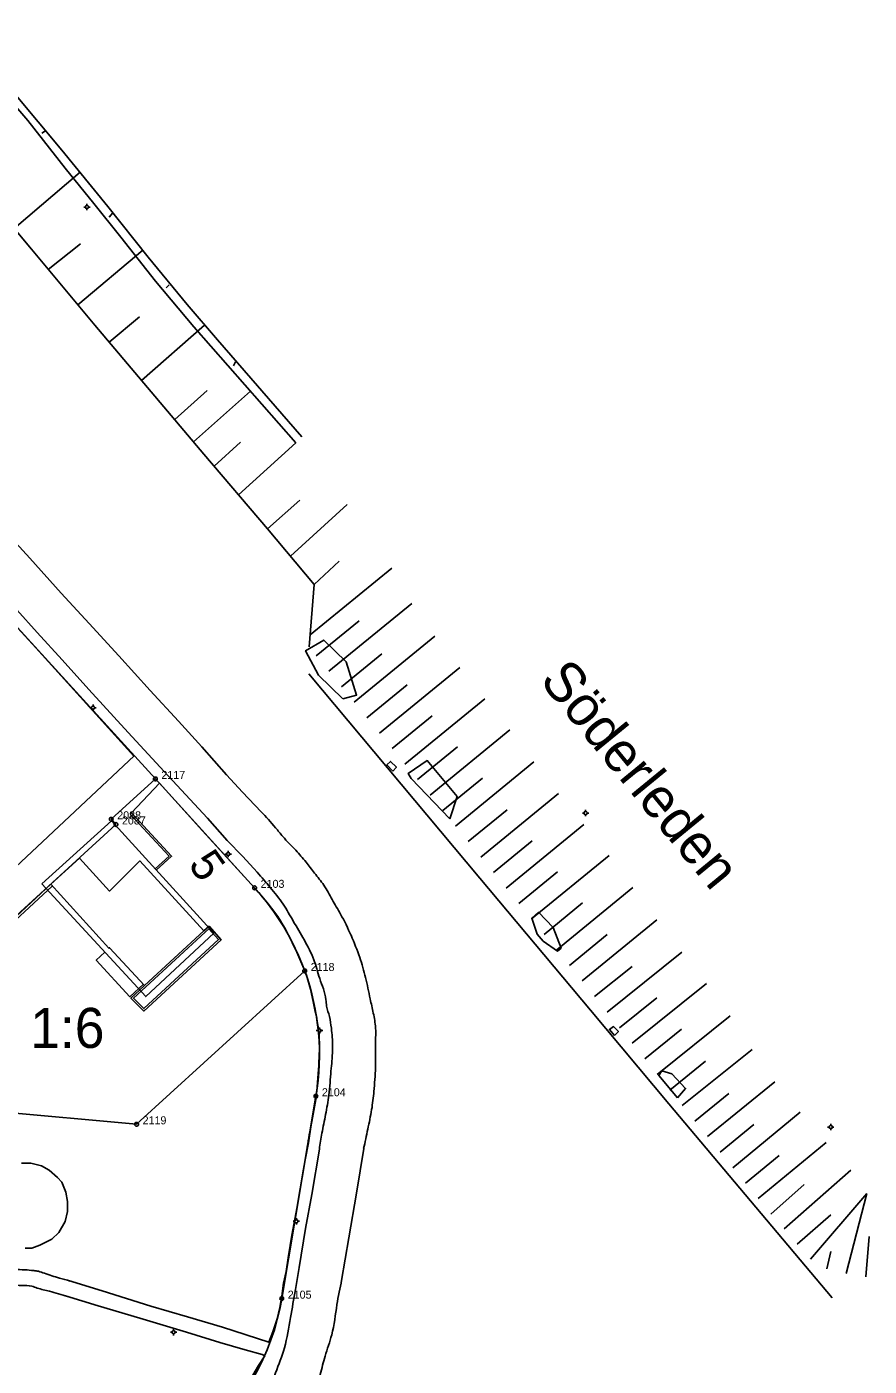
# Model space of a CAD drawing. Extents: x 1517693 to 1518189, y 6494860 to 6495280.
# Drawn here: x 1518083.9 to 1518189.2, y 6495063.4 to 6495230.8 of the extents above; entities that cross this region are included whole.
import ezdxf

# ---------------------------------------------------------------- set-up
doc = ezdxf.new("R2010")
doc.units = 0
for name, color, linetype in [('adress', 7, 'Continuous'), ('bostadshus', 7, 'Continuous'), ('fastighetsbeteckning', 7, 'Continuous'), ('gatunamn', 7, 'Continuous'), ('gc_vag', 7, 'Continuous'), ('grans', 7, 'Continuous'), ('granspunkt', 7, 'Continuous'), ('granspunkt_text', 7, 'Continuous'), ('kvartersgrans', 7, 'Continuous'), ('kvartersgrans_utan_fastgr', 7, 'Continuous'), ('planteringskant', 7, 'Continuous'), ('skarmtak', 7, 'Continuous'), ('slant_skraffering', 7, 'Continuous'), ('slantfot', 7, 'Continuous'), ('slantkron', 7, 'Continuous'), ('staket', 7, 'Continuous'), ('stenmur', 7, 'Continuous'), ('stolpe_belysning', 7, 'Continuous'), ('trappa_byggnad', 7, 'Continuous'), ('vagkant', 7, 'Continuous')]:
    doc.layers.add(name, color=color, linetype=linetype)

msp = doc.modelspace()

# ---------------------------------------------------------------- linework, layer by layer
at = {"layer": 'bostadshus'}
msp.add_lwpolyline([(1518086.89, 6495123.66), (1518090.48, 6495126.91), (1518094.25, 6495122.81), (1518098.04, 6495126.57), (1518106.03, 6495117.83), (1518098.62, 6495111.02), (1518094.24, 6495115.73), (1518094.15, 6495115.66), (1518086.88, 6495123.66)], dxfattribs=at)
at = {"layer": 'gc_vag'}
for p, q in [((1518085.02, 6495153.19), (1518097.28, 6495139.69)), ((1518100.47, 6495136.3), (1518096.97, 6495132.58))]:
    msp.add_line(p, q, dxfattribs=at)
for points in [[(1518080.55, 6495158.09), (1518082.73, 6495155.72), (1518085.02, 6495153.19)], [(1518097.3, 6495139.7), (1518079.77, 6495123.29), (1518069.67, 6495123.88)], [(1518100.47, 6495136.3), (1518105.84, 6495130.34), (1518112.4, 6495123.17)], [(1518118.38, 6495087.34), (1518118.71, 6495089.22), (1518119.1, 6495091.32), (1518119.41, 6495093.33), (1518119.63, 6495094.49)], [(1518116.59, 6495076.95), (1518117.01, 6495079.78), (1518117.66, 6495083.14), (1518118.07, 6495085.6), (1518118.38, 6495087.34)], [(1518108.34, 6495068.28), (1518114.17, 6495066.44), (1518114.67, 6495067.72), (1518115.19, 6495069.34), (1518115.54, 6495070.77), (1518115.78, 6495072.17), (1518116, 6495073.78), (1518116.31, 6495075.24), (1518116.59, 6495076.95)], [(1518089.11, 6495074.12), (1518093.31, 6495072.82), (1518099.4, 6495070.92), (1518104, 6495069.59), (1518108.36, 6495068.28)], [(1518088.71, 6495072.21), (1518092.82, 6495070.95), (1518098.04, 6495069.4), (1518103.85, 6495067.66), (1518108.04, 6495066.38)], [(1518108.04, 6495066.38), (1518111.18, 6495065.48), (1518113.3, 6495064.86), (1518113.64, 6495064.7), (1518112.86, 6495063.49), (1518112.15, 6495062.31), (1518111.37, 6495061.1), (1518110.56, 6495059.64), (1518109.72, 6495058.67), (1518108.98, 6495057.52), (1518108.11, 6495056.71)]]:
    msp.add_lwpolyline(points, dxfattribs=at)
for points in [[(1518112.4, 6495123.17), (1518115.62, 6495119.07), (1518117.64, 6495115.15), (1518118.65, 6495112.85), (1518119.88, 6495108.19), (1518120.44, 6495104.77), (1518120.39, 6495101.02)], [(1518120.39, 6495101.02), (1518120.02, 6495096.76), (1518119.35, 6495093.11), (1518118.85, 6495090.03)], [(1518088.99, 6495072.13), (1518086.72, 6495072.79), (1518085.2, 6495073.19), (1518084.51, 6495073.41), (1518083.27, 6495073.5), (1518081.87, 6495073.63), (1518080.97, 6495073.75), (1518080.47, 6495073.72), (1518079.88, 6495073.88), (1518078.58, 6495074.53), (1518076.65, 6495075.37), (1518074.29, 6495076.36), (1518073.26, 6495076.67), (1518072.74, 6495076.83), (1518072.14, 6495076.77), (1518070.78, 6495076.61), (1518069.5, 6495076.46), (1518067.92, 6495076.27), (1518066.49, 6495076.08), (1518065.28, 6495076.18), (1518064.28, 6495076.46), (1518063.29, 6495076.64), (1518062.85, 6495076.98), (1518062.17, 6495077.67), (1518061.8, 6495078.01), (1518061.36, 6495078.57)], [(1518076.25, 6495077.92), (1518078.76, 6495076.61), (1518080.01, 6495076.02), (1518081.13, 6495075.77), (1518082.34, 6495075.55), (1518083.64, 6495075.46), (1518084.76, 6495075.37), (1518085.35, 6495075.28), (1518086.1, 6495075.03), (1518087.96, 6495074.44), (1518089.3, 6495074.06)]]:
    msp.add_spline(points, degree=3, dxfattribs=at)
at = {"layer": 'grans'}
for p, q in [((1518094.45, 6495131.78), (1518099.97, 6495136.82)), ((1518099.97, 6495136.82), (1518112.38, 6495123.21)), ((1518095.04, 6495131.13), (1518094.45, 6495131.78)), ((1518079.46, 6495116.91), (1518095.04, 6495131.13)), ((1518118.64, 6495112.82), (1518097.62, 6495093.65)), ((1518097.62, 6495093.65), (1518075.29, 6495095.71))]:
    msp.add_line(p, q, dxfattribs=at)
msp.add_arc((1518089.46, 6495102.3), 31.02, 19.8209, 42.3652, dxfattribs=at)
at = {"layer": 'granspunkt'}
for centre in [(1518099.97, 6495136.82), (1518094.45, 6495131.78), (1518095.04, 6495131.13), (1518112.38, 6495123.21), (1518118.64, 6495112.82), (1518120.04, 6495097.16), (1518097.62, 6495093.65), (1518115.77, 6495071.86)]:
    msp.add_circle(centre, 0.237, dxfattribs=at)
at = {"layer": 'kvartersgrans'}
msp.add_line((1518099.97, 6495136.82), (1518112.38, 6495123.21), dxfattribs=at)
msp.add_arc((1518089.46, 6495102.3), 31.02, 19.8209, 42.3652, dxfattribs=at)
at = {"layer": 'kvartersgrans_utan_fastgr'}
for p, q in [((1518073.64, 6495165.68), (1518099.97, 6495136.82)), ((1518115.77, 6495071.86), (1518120.04, 6495097.16))]:
    msp.add_line(p, q, dxfattribs=at)
for centre, radius, start, end in [((1518089.47, 6495102.32), 31.01, 350.4256, 19.8012), ((1518086.18, 6495076.85), 30.01, 309.8505, 350.4132)]:
    msp.add_arc(centre, radius, start, end, dxfattribs=at)
at = {"layer": 'planteringskant'}
for points in [[(1518123.4, 6495146.83), (1518125.12, 6495147.31), (1518123.83, 6495151.48), (1518121.03, 6495154.17), (1518118.74, 6495152.84), (1518120.38, 6495149.78), (1518123.4, 6495146.83)], [(1518129.67, 6495137.81), (1518130.1, 6495138.28), (1518129.37, 6495139.01), (1518128.91, 6495138.6), (1518129.67, 6495137.81)], [(1518136.79, 6495131.84), (1518137.69, 6495134.62), (1518133.96, 6495139.12), (1518131.58, 6495137.52), (1518131.95, 6495136.86), (1518136.79, 6495131.84)], [(1518148.45, 6495116.56), (1518150.25, 6495115.31), (1518150.7, 6495115.68), (1518149.7, 6495118.24), (1518147.86, 6495120.16), (1518147.03, 6495119.44), (1518147.69, 6495117.42), (1518148.45, 6495116.56)], [(1518157.39, 6495104.74), (1518157.86, 6495105.24), (1518157.24, 6495105.86), (1518156.75, 6495105.51), (1518157.39, 6495104.74)], [(1518165.24, 6495096.98), (1518166.27, 6495098.14), (1518164.55, 6495099.95), (1518163.31, 6495100.33), (1518162.9, 6495099.77), (1518165.24, 6495096.98)], [(1518083.21, 6495088.81), (1518084.39, 6495088.81), (1518085.71, 6495088.47), (1518086.68, 6495087.93), (1518087.74, 6495087.02), (1518088.28, 6495086.42), (1518088.76, 6495085.18), (1518089, 6495084), (1518089, 6495082.77), (1518088.67, 6495081.5), (1518087.89, 6495080.14), (1518087.01, 6495079.29), (1518085.53, 6495078.54), (1518084.54, 6495078.18), (1518083.69, 6495078.15)]]:
    msp.add_lwpolyline(points, dxfattribs=at)
at = {"layer": 'skarmtak'}
for points in [[(1518085.76, 6495123.72), (1518094.48, 6495131.58), (1518107.27, 6495117.56)], [(1518107.27, 6495117.56), (1518098.76, 6495109.61), (1518085.76, 6495123.72)]]:
    msp.add_lwpolyline(points, dxfattribs=at)
at = {"layer": 'slant_skraffering'}
for p, q in [((1518086.24, 6495217.85), (1518085.78, 6495217.53)), ((1518082.3, 6495205.63), (1518090.55, 6495212.65)), ((1518094.66, 6495207.6), (1518094.2, 6495207.05)), ((1518086.57, 6495200.51), (1518090.61, 6495203.72)), ((1518090.27, 6495196.07), (1518098.38, 6495202.9)), ((1518101.7, 6495198.59), (1518101.3, 6495198.19)), ((1518094.19, 6495191.4), (1518097.97, 6495194.59)), ((1518098.24, 6495186.62), (1518106.09, 6495193.55)), ((1518110, 6495188.94), (1518109.72, 6495188.44)), ((1518102.38, 6495181.75), (1518106.46, 6495185.36)), ((1518104.74, 6495178.96), (1518111.87, 6495185.29)), ((1518107.33, 6495175.92), (1518110.62, 6495178.9)), ((1518110.38, 6495172.32), (1518117.53, 6495178.85)), ((1518113.99, 6495168.08), (1518118.04, 6495171.67)), ((1518116.85, 6495164.68), (1518123.96, 6495171.13)), ((1518119.84, 6495161.12), (1518122.96, 6495164.03)), ((1518119.31, 6495154.82), (1518129.53, 6495163.17)), ((1518121.67, 6495150.29), (1518132.04, 6495158.77)), ((1518120.09, 6495152.22), (1518125.44, 6495156.6)), ((1518124.84, 6495146.42), (1518134.91, 6495154.65)), ((1518123.25, 6495148.35), (1518128.3, 6495152.48)), ((1518128, 6495142.55), (1518138.02, 6495150.74)), ((1518126.42, 6495144.48), (1518131.44, 6495148.59)), ((1518131.17, 6495138.68), (1518141.15, 6495146.84)), ((1518129.58, 6495140.61), (1518134.58, 6495144.7)), ((1518134.33, 6495134.8), (1518144.28, 6495142.94)), ((1518132.75, 6495136.74), (1518137.73, 6495140.82)), ((1518137.5, 6495130.93), (1518147.31, 6495138.96)), ((1518135.91, 6495132.87), (1518140.86, 6495136.91)), ((1518140.66, 6495127.06), (1518150.36, 6495134.99)), ((1518139.08, 6495129), (1518143.94, 6495132.98)), ((1518143.83, 6495123.19), (1518153.53, 6495131.13)), ((1518142.24, 6495125.13), (1518147.09, 6495129.09)), ((1518146.99, 6495119.32), (1518156.7, 6495127.26)), ((1518145.41, 6495121.26), (1518150.26, 6495125.23)), ((1518150.16, 6495115.45), (1518159.68, 6495123.24)), ((1518148.57, 6495117.39), (1518153.38, 6495121.32)), ((1518153.32, 6495111.58), (1518162.65, 6495119.21)), ((1518151.74, 6495113.52), (1518156.45, 6495117.37)), ((1518156.45, 6495107.68), (1518165.79, 6495115.18)), ((1518154.89, 6495109.63), (1518159.57, 6495113.39)), ((1518159.58, 6495103.78), (1518168.86, 6495111.24)), ((1518158.02, 6495105.73), (1518162.67, 6495109.47)), ((1518162.71, 6495099.89), (1518171.84, 6495107.22)), ((1518161.15, 6495101.83), (1518165.77, 6495105.55)), ((1518164.28, 6495097.94), (1518168.75, 6495101.53)), ((1518165.84, 6495095.99), (1518174.6, 6495103.02)), ((1518169, 6495092.11), (1518177.41, 6495098.96)), ((1518167.42, 6495094.05), (1518171.68, 6495097.52)), ((1518172.16, 6495088.23), (1518180.58, 6495095.15)), ((1518170.58, 6495090.17), (1518174.79, 6495093.61)), ((1518175.34, 6495084.37), (1518183.85, 6495091.37)), ((1518173.75, 6495086.3), (1518177.97, 6495089.77)), ((1518178.58, 6495080.57), (1518186.94, 6495087.9)), ((1518176.93, 6495082.44), (1518181.1, 6495086.11)), ((1518181.87, 6495076.81), (1518188.94, 6495085)), ((1518186.35, 6495075), (1518188.94, 6495085)), ((1518180.23, 6495078.69), (1518184.41, 6495082.35)), ((1518188.8, 6495074.57), (1518189.23, 6495079.64)), ((1518183.91, 6495075.58), (1518184.43, 6495077.74))]:
    msp.add_line(p, q, dxfattribs=at)
at = {"layer": 'slantfot'}
for points in [[(1518092.27, 6495208.77), (1518088.68, 6495213.17), (1518084, 6495219.13), (1518078.82, 6495225.16), (1518074.04, 6495230.84)], [(1518117.53, 6495178.85), (1518104.79, 6495193.34), (1518100, 6495199.05), (1518095.64, 6495204.55), (1518092.27, 6495208.77)]]:
    msp.add_lwpolyline(points, dxfattribs=at)
at = {"layer": 'slantkron'}
msp.add_lwpolyline([(1518119.18, 6495153.33), (1518119.84, 6495161.12), (1518113.99, 6495168.08)], dxfattribs=at)
at = {"layer": 'staket'}
msp.add_line((1518140.54, 6495124.4), (1518119.15, 6495149.98), dxfattribs=at)
for points in [[(1518074.17, 6495215.34), (1518084.47, 6495203.04), (1518092.38, 6495193.53)], [(1518092.38, 6495193.53), (1518106.04, 6495177.43), (1518113.99, 6495168.08)], [(1518140.54, 6495124.4), (1518154.39, 6495107.9), (1518164.18, 6495096.23), (1518184.61, 6495071.96)]]:
    msp.add_lwpolyline(points, dxfattribs=at)
at = {"layer": 'stenmur'}
for p, q in [((1518096.97, 6495132.58), (1518096.82, 6495132.43)), ((1518106.18, 6495117.67), (1518098.77, 6495110.84))]:
    msp.add_line(p, q, dxfattribs=at)
for points in [[(1518096.81, 6495132.43), (1518101.68, 6495127.17), (1518099.94, 6495125.6)], [(1518096.97, 6495132.58), (1518101.99, 6495127.16), (1518100.08, 6495125.44)], [(1518068.15, 6495117.91), (1518079.47, 6495116.8), (1518086.88, 6495123.66)], [(1518068.17, 6495117.6), (1518079.57, 6495116.49), (1518087.08, 6495123.44)], [(1518106.03, 6495117.83), (1518106.68, 6495118.41), (1518108.19, 6495116.73), (1518098.53, 6495107.81), (1518096.9, 6495109.44), (1518098.62, 6495111.01)], [(1518106.18, 6495117.67), (1518106.66, 6495118.1), (1518107.87, 6495116.75), (1518098.53, 6495108.12), (1518097.22, 6495109.43), (1518098.77, 6495110.84)]]:
    msp.add_lwpolyline(points, dxfattribs=at)
at = {"layer": 'stolpe_belysning'}
for p, q in [((1518091.41, 6495208.51), (1518091.41, 6495208.71)), ((1518091.21, 6495208.31), (1518091.01, 6495208.31)), ((1518091.41, 6495208.11), (1518091.41, 6495207.91)), ((1518091.61, 6495208.31), (1518091.81, 6495208.31)), ((1518091.97, 6495145.73), (1518091.77, 6495145.73)), ((1518092.17, 6495145.93), (1518092.17, 6495146.13)), ((1518092.17, 6495145.53), (1518092.17, 6495145.33)), ((1518092.37, 6495145.73), (1518092.57, 6495145.73)), ((1518153.56, 6495132.55), (1518153.36, 6495132.55)), ((1518153.76, 6495132.75), (1518153.76, 6495132.95)), ((1518153.76, 6495132.35), (1518153.76, 6495132.15)), ((1518153.96, 6495132.55), (1518154.16, 6495132.55)), ((1518108.87, 6495127.44), (1518108.67, 6495127.44)), ((1518109.07, 6495127.64), (1518109.07, 6495127.84)), ((1518109.07, 6495127.24), (1518109.07, 6495127.04)), ((1518109.27, 6495127.44), (1518109.47, 6495127.44)), ((1518120.29, 6495105.37), (1518120.09, 6495105.37)), ((1518120.49, 6495105.57), (1518120.49, 6495105.77)), ((1518120.49, 6495105.17), (1518120.49, 6495104.97)), ((1518120.69, 6495105.37), (1518120.89, 6495105.37)), ((1518184.22, 6495093.31), (1518184.02, 6495093.31)), ((1518184.42, 6495093.51), (1518184.42, 6495093.71)), ((1518184.62, 6495093.31), (1518184.82, 6495093.31)), ((1518184.42, 6495093.11), (1518184.42, 6495092.91)), ((1518117.4, 6495081.53), (1518117.2, 6495081.53)), ((1518117.6, 6495081.73), (1518117.6, 6495081.93)), ((1518117.8, 6495081.53), (1518118, 6495081.53)), ((1518117.6, 6495081.33), (1518117.6, 6495081.13)), ((1518102.24, 6495067.87), (1518102.24, 6495068.07)), ((1518102.04, 6495067.67), (1518101.84, 6495067.67)), ((1518102.24, 6495067.47), (1518102.24, 6495067.27)), ((1518102.44, 6495067.67), (1518102.64, 6495067.67))]:
    msp.add_line(p, q, dxfattribs=at)
for centre in [(1518091.41, 6495208.31), (1518092.17, 6495145.73), (1518153.76, 6495132.55), (1518109.07, 6495127.44), (1518120.49, 6495105.37), (1518184.42, 6495093.31), (1518117.6, 6495081.53), (1518102.24, 6495067.67)]:
    msp.add_circle(centre, 0.2, dxfattribs=at)
at = {"layer": 'trappa_byggnad'}
msp.add_lwpolyline([(1518093.65, 6495115.16), (1518092.58, 6495114.18), (1518096.79, 6495109.6), (1518098.49, 6495111.15)], dxfattribs=at)
at = {"layer": 'vagkant'}
for points in [[(1518094.04, 6495208.38), (1518088.29, 6495215.41), (1518082.34, 6495222.5), (1518075.88, 6495230.24)], [(1518118.28, 6495179.58), (1518107.73, 6495191.71), (1518103.93, 6495196.14), (1518099.08, 6495202.03), (1518094.04, 6495208.38)], [(1518069.53, 6495180.63), (1518073.11, 6495176.72), (1518077.69, 6495171.65), (1518081.2, 6495167.8), (1518084.26, 6495164.41)], [(1518077.08, 6495164.11), (1518080.05, 6495160.8), (1518085.2, 6495155.13), (1518088.32, 6495151.7), (1518091.63, 6495148.01)], [(1518084.26, 6495164.41), (1518088.2, 6495160.04), (1518091.69, 6495156.25), (1518095.39, 6495152.22), (1518099.3, 6495147.88)], [(1518091.63, 6495148.01), (1518096.57, 6495142.61), (1518101.57, 6495137.21), (1518106.48, 6495131.94)], [(1518099.3, 6495147.88), (1518102.84, 6495144.03), (1518105.78, 6495140.82), (1518108.84, 6495137.33), (1518110.87, 6495135.18), (1518113.18, 6495132.73)], [(1518106.48, 6495131.94), (1518108.96, 6495129.12), (1518110.9, 6495127.12), (1518112.69, 6495125.15)], [(1518120.47, 6495090.56), (1518119.53, 6495084.88), (1518118.75, 6495080.62), (1518117.94, 6495075.74), (1518117.47, 6495073)], [(1518126.02, 6495090.64), (1518125.12, 6495085.04), (1518124.16, 6495079.47), (1518123.25, 6495074.12)]]:
    msp.add_lwpolyline(points, dxfattribs=at)
for points in [[(1518113.18, 6495132.73), (1518114.99, 6495130.72), (1518115.9, 6495129.63), (1518117.51, 6495127.9), (1518118.81, 6495126.42), (1518119.87, 6495125.05), (1518121.03, 6495123.54), (1518122.06, 6495121.75), (1518123.12, 6495119.93), (1518124.45, 6495117.26)], [(1518112.69, 6495125.15), (1518114.33, 6495123.27), (1518115.93, 6495121.17), (1518117.21, 6495119.05), (1518118.6, 6495116.69)], [(1518118.6, 6495116.69), (1518119.77, 6495114.23), (1518120.52, 6495111.89), (1518121.29, 6495109.23), (1518121.38, 6495108.44), (1518121.73, 6495107.11), (1518121.97, 6495105.66), (1518122.13, 6495103.44), (1518122.04, 6495101.59), (1518121.92, 6495100.31)], [(1518124.44, 6495117.28), (1518125.53, 6495114.5), (1518126.25, 6495111.99), (1518126.83, 6495109.32), (1518127.22, 6495107.56), (1518127.5, 6495105.71), (1518127.5, 6495104.01), (1518127.5, 6495102.5), (1518127.5, 6495100.62)], [(1518121.92, 6495100.34), (1518121.65, 6495097.31), (1518121.25, 6495094.86), (1518120.8, 6495092.55), (1518120.47, 6495090.55)], [(1518127.5, 6495100.77), (1518127.29, 6495097.77), (1518127.01, 6495095.49), (1518126.53, 6495093.04), (1518126.01, 6495090.61)], [(1518123.26, 6495074.18), (1518122.67, 6495071.12), (1518122.02, 6495067.34), (1518121.18, 6495064.67), (1518120.59, 6495062.39), (1518119.88, 6495059.98), (1518118.71, 6495057.18), (1518117.14, 6495054.45), (1518115.84, 6495052.37), (1518114.09, 6495049.96), (1518112.13, 6495047.35), (1518110.51, 6495045.6), (1518108.82, 6495043.9), (1518107.64, 6495042.54)], [(1518117.47, 6495073), (1518116.88, 6495069.49), (1518116.1, 6495065.71), (1518115, 6495062.59), (1518113.76, 6495059.66), (1518112.78, 6495057.77), (1518111.68, 6495055.82), (1518110.38, 6495053.67), (1518108.62, 6495051.39), (1518107.25, 6495049.7), (1518106.15, 6495048.59), (1518105.24, 6495047.55), (1518104.02, 6495046.63)]]:
    msp.add_spline(points, degree=3, dxfattribs=at)

# ---------------------------------------------------------------- texts
at = {"layer": 'adress'}
msp.add_text('5', height=4, rotation=305.5194, dxfattribs=at).set_placement((1518103.98, 6495126.11))
at = {"layer": 'fastighetsbeteckning'}
msp.add_text('1:6', height=5, rotation=0.0021, dxfattribs=at).set_placement((1518084.31, 6495103.2))
at = {"layer": 'gatunamn'}
msp.add_text('Söderleden', height=5, rotation=309.3524, dxfattribs=at).set_placement((1518147.89, 6495149.09))
at = {"layer": 'granspunkt_text'}
for s, p in [('2117', (1518100.72, 6495136.82)), ('2088', (1518095.2, 6495131.78)), ('2087', (1518095.79, 6495131.13)), ('2103', (1518113.13, 6495123.21)), ('2118', (1518119.39, 6495112.82)), ('2104', (1518120.79, 6495097.16)), ('2119', (1518098.37, 6495093.65)), ('2105', (1518116.52, 6495071.86))]:
    msp.add_text(s, height=1, dxfattribs=at).set_placement(p)

doc.saveas('drawing.dxf')
